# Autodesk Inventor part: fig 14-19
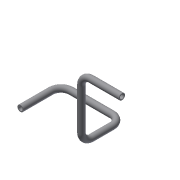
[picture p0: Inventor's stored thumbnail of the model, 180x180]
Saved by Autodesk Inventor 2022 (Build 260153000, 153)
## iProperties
Created: 2005-03
Part Number: fig 14-19
Document SubType Name: Modeling
Designer: CADCIM
Manufacturer: Standard
Standards Organization: Custom
Density: 1 g/cm^3
Material: Generic
Appearance: Default
Author: CADCIM
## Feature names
1. Sweep1
## Parameters: d9 = 6 mm, d10 = 4 mm, d11 = 0, d12 = 0
